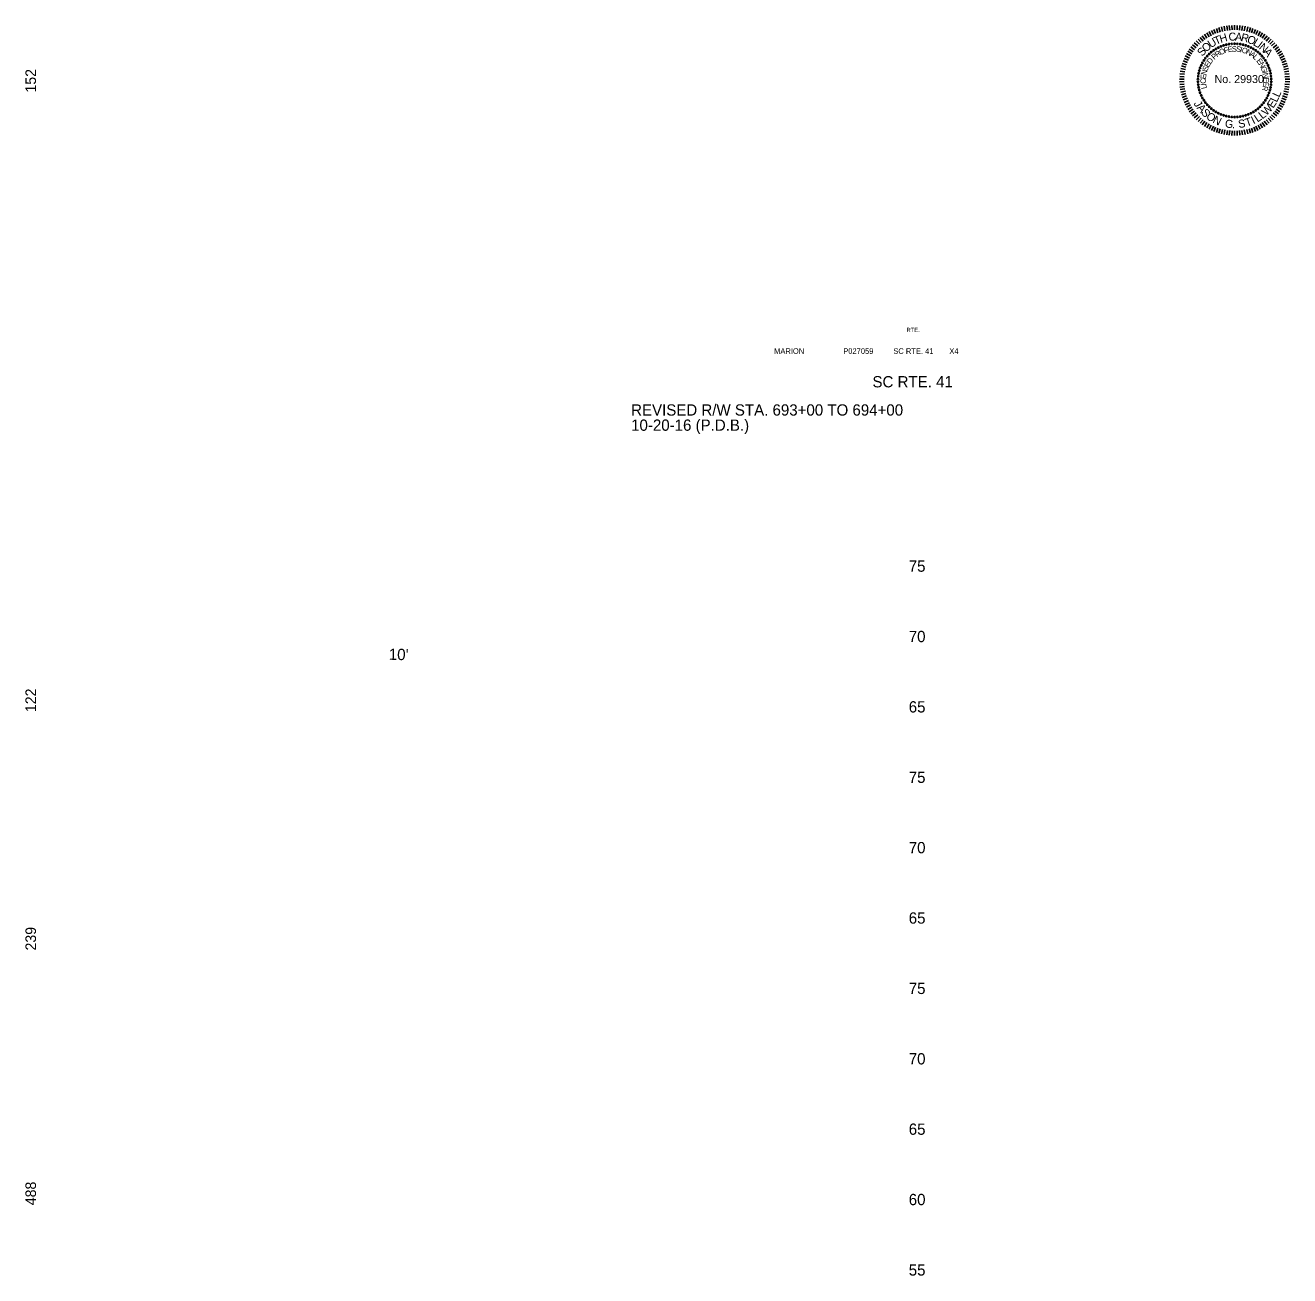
# Model space of a CAD drawing. Extents: x 952 to 1206, y 942 to 2399.
# Drawn here: x 1094.2 to 1184, y 1955 to 2043.8 of the extents above; entities that cross this region are included whole.
import ezdxf

# ---------------------------------------------------------------- set-up
doc = ezdxf.new("R2010")
doc.units = 0
for name, color, linetype in [('Default', 7, 'Continuous'), ('RD_SHT_TX', 7, 'Continuous'), ('RD_TX_PEShield', 7, 'Continuous'), ('RD_XS_TX_Elev_EX', 7, 'Continuous'), ('RD_XS_TX_Slope', 7, 'Continuous')]:
    doc.layers.add(name, color=color, linetype=linetype)

# ---------------------------------------------------------------- blocks, each defined once
blk = doc.blocks.new('STILLWELL')
at = {"layer": 'RD_TX_PEShield'}
for p, q in [((-11.93, 32.91), (-13.02, 35.99)), ((-10.28, 33.44), (-11.22, 36.57)), ((-8.61, 33.9), (-9.39, 37.07)), ((-6.92, 34.27), (-7.55, 37.48)), ((-5.21, 34.57), (-5.68, 37.8)), ((-3.49, 34.77), (-3.81, 38.03)), ((-1.76, 34.9), (-1.92, 38.16)), ((-0.03, 34.94), (-0.03, 38.21)), ((1.71, 34.9), (1.86, 38.16)), ((3.43, 34.77), (3.75, 38.03)), ((5.15, 34.57), (5.63, 37.8)), ((6.86, 34.27), (7.49, 37.48)), ((8.56, 33.9), (9.34, 37.07)), ((10.23, 33.44), (11.16, 36.57)), ((11.88, 32.91), (12.96, 35.99)), ((-25.08, 24.74), (-27.37, 27.08)), ((-23.81, 25.92), (-25.98, 28.37)), ((-22.49, 27.04), (-24.53, 29.59)), ((-21.11, 28.09), (-23.03, 30.73)), ((-19.68, 29.08), (-21.48, 31.81)), ((-18.21, 29.99), (-19.87, 32.81)), ((-16.7, 30.83), (-18.22, 33.73)), ((-15.14, 31.6), (-16.52, 34.56)), ((-13.55, 32.29), (-14.79, 35.32)), ((13.5, 32.29), (14.73, 35.32)), ((15.09, 31.6), (16.46, 34.56)), ((16.64, 30.83), (18.16, 33.73)), ((18.16, 29.99), (19.81, 32.81)), ((19.63, 29.08), (21.42, 31.81)), ((21.06, 28.09), (22.98, 30.73)), ((22.43, 27.04), (24.48, 29.59)), ((23.76, 25.92), (25.92, 28.37)), ((25.03, 24.74), (27.31, 27.08)), ((-31.38, 16.5), (-34.23, 18.09)), ((-30.5, 18), (-33.27, 19.72)), ((-29.55, 19.45), (-32.24, 21.3)), ((-28.53, 20.85), (-31.12, 22.83)), ((-27.44, 22.2), (-29.94, 24.31)), ((-26.29, 23.5), (-28.69, 25.72)), ((26.24, 23.5), (28.63, 25.72)), ((27.39, 22.2), (29.88, 24.31)), ((28.47, 20.85), (31.07, 22.83)), ((29.49, 19.45), (32.18, 21.3)), ((30.44, 18), (33.22, 19.72)), ((31.32, 16.5), (34.18, 18.09)), ((-34.64, 8.5), (-37.79, 9.35)), ((-34.14, 10.16), (-37.25, 11.17)), ((-33.57, 11.79), (-36.62, 12.95)), ((-32.91, 13.4), (-35.91, 14.7)), ((-32.18, 14.97), (-35.11, 16.42)), ((32.13, 14.97), (35.06, 16.42)), ((32.86, 13.4), (35.85, 14.7)), ((33.51, 11.79), (36.57, 12.95)), ((34.09, 10.16), (37.19, 11.17)), ((34.58, 8.5), (37.73, 9.35)), ((-35.89, -0.06), (-39.15, 0.02)), ((-35.8, 1.67), (-39.06, 1.91)), ((-35.64, 3.4), (-38.88, 3.79)), ((-35.39, 5.11), (-38.61, 5.66)), ((-35.05, 6.81), (-38.24, 7.52)), ((35, 6.81), (38.19, 7.52)), ((35.33, 5.11), (38.55, 5.66)), ((35.58, 3.4), (38.82, 3.79)), ((35.75, 1.67), (39.01, 1.91)), ((35.83, -0.06), (39.1, 0.02)), ((-35.89, -1.79), (-39.15, -1.87)), ((-35.8, -3.53), (-39.06, -3.76)), ((-35.64, -5.25), (-38.88, -5.65)), ((-35.39, -6.97), (-38.61, -7.52)), ((-35.05, -8.67), (-38.24, -9.37)), ((35, -8.67), (38.19, -9.37)), ((35.33, -6.97), (38.55, -7.52)), ((35.58, -5.25), (38.82, -5.65)), ((35.75, -3.53), (39.01, -3.76)), ((35.83, -1.79), (39.1, -1.87)), ((-34.64, -10.35), (-37.79, -11.21)), ((-34.14, -12.01), (-37.25, -13.02)), ((-33.57, -13.65), (-36.62, -14.81)), ((-32.91, -15.25), (-35.91, -16.56)), ((-32.18, -16.83), (-35.11, -18.27)), ((32.13, -16.83), (35.06, -18.27)), ((32.86, -15.25), (35.85, -16.56)), ((33.51, -13.65), (36.57, -14.81)), ((34.09, -12.01), (37.19, -13.02)), ((34.58, -10.35), (37.73, -11.21)), ((-31.38, -18.36), (-34.23, -19.95)), ((-30.5, -19.85), (-33.27, -21.58)), ((-29.55, -21.3), (-32.24, -23.16)), ((-28.53, -22.71), (-31.12, -24.69)), ((-27.44, -24.06), (-29.94, -26.16)), ((-26.29, -25.36), (-28.69, -27.58)), ((-25.08, -26.6), (-27.37, -28.93)), ((25.03, -26.6), (27.31, -28.93)), ((26.24, -25.36), (28.63, -27.58)), ((27.39, -24.06), (29.88, -26.16)), ((28.47, -22.71), (31.07, -24.69)), ((29.49, -21.3), (32.18, -23.16)), ((30.44, -19.85), (33.22, -21.58)), ((31.32, -18.36), (34.18, -19.95)), ((-23.81, -27.78), (-25.98, -30.22)), ((-22.49, -28.89), (-24.53, -31.44)), ((-21.11, -29.95), (-23.03, -32.59)), ((-19.68, -30.93), (-21.48, -33.66)), ((-18.21, -31.85), (-19.87, -34.66)), ((-16.7, -32.69), (-18.22, -35.58)), ((-15.14, -33.46), (-16.52, -36.42)), ((-13.55, -34.15), (-14.79, -37.18)), ((-11.93, -34.76), (-13.02, -37.85)), ((-10.28, -35.3), (-11.22, -38.43)), ((-8.61, -35.76), (-9.39, -38.93)), ((8.56, -35.76), (9.34, -38.93)), ((10.23, -35.3), (11.16, -38.43)), ((11.88, -34.76), (12.96, -37.85)), ((13.5, -34.15), (14.73, -37.18)), ((15.09, -33.46), (16.46, -36.42)), ((16.64, -32.69), (18.16, -35.58)), ((18.16, -31.85), (19.81, -34.66)), ((19.63, -30.93), (21.42, -33.66)), ((21.06, -29.95), (22.98, -32.59)), ((22.43, -28.89), (24.48, -31.44)), ((23.76, -27.78), (25.92, -30.22)), ((-6.92, -36.13), (-7.55, -39.34)), ((-5.21, -36.42), (-5.68, -39.65)), ((-3.49, -36.63), (-3.81, -39.88)), ((-1.76, -36.76), (-1.92, -40.02)), ((-0.03, -36.8), (-0.03, -40.06)), ((1.71, -36.76), (1.86, -40.02)), ((3.43, -36.63), (3.75, -39.88)), ((5.15, -36.42), (5.63, -39.65)), ((6.86, -36.13), (7.49, -39.34))]:
    blk.add_line(p, q, dxfattribs=at)
for centre in [(-18.09, 17.84), (-16.6, 19.17), (-15.01, 20.38), (-13.34, 21.46), (-11.59, 22.41), (-9.76, 23.23), (-7.89, 23.9), (-5.96, 24.43), (-4, 24.81), (-2.02, 25.04), (-0.03, 25.12), (1.97, 25.04), (3.95, 24.81), (5.91, 24.43), (7.83, 23.9), (9.71, 23.23), (11.53, 22.41), (13.28, 21.46), (14.96, 20.38), (16.54, 19.17), (18.03, 17.84), (-23.79, 9.73), (-22.91, 11.51), (-21.89, 13.23), (-20.74, 14.86), (-19.47, 16.4), (19.42, 16.4), (20.69, 14.86), (21.83, 13.23), (22.85, 11.51), (23.74, 9.73), (-26.05, 0.07), (-25.9, 2.06), (-25.6, 4.03), (-25.14, 5.97), (-24.54, 7.88), (24.48, 7.88), (25.09, 5.97), (25.54, 4.03), (25.85, 2.06), (26, 0.07), (-26.05, -1.93), (-25.9, -3.92), (-25.6, -5.89), (-25.14, -7.83), (25.09, -7.83), (25.54, -5.89), (25.85, -3.92), (26, -1.93), (-24.54, -9.73), (-23.79, -11.58), (-22.91, -13.37), (-21.89, -15.09), (-20.74, -16.72), (-19.47, -18.26), (19.42, -18.26), (20.69, -16.72), (21.83, -15.09), (22.85, -13.37), (23.74, -11.58), (24.48, -9.73), (-18.09, -19.69), (-16.6, -21.02), (-15.01, -22.23), (-13.34, -23.32), (-11.59, -24.27), (-9.76, -25.09), (-7.89, -25.76), (-5.96, -26.29), (-4, -26.67), (-2.02, -26.9), (-0.03, -26.97), (1.97, -26.9), (3.95, -26.67), (5.91, -26.29), (7.83, -25.76), (9.71, -25.09), (11.53, -24.27), (13.28, -23.32), (14.96, -22.23), (16.54, -21.02), (18.03, -19.69)]:
    blk.add_circle(centre, 0.49, dxfattribs=at)
for s, height, rotation, p in [('U', 5.68, 32.21524, (-16.89, 21.85)), ('T', 5.68, 23.50438, (-13.24, 24.14)), ('H', 5.68, 16.13567, (-9.92, 25.63)), ('C', 5.68, 4.07599, (-4.15, 27.11)), ('A', 5.68, 355.36513, (0.14, 27.41)), ('R', 5.68, 347.31877, (4.1, 27.11)), ('O', 5.68, 338.6079, (8.3, 26.16)), ('L', 5.68, 329.22596, (12.61, 24.44)), ('S', 5.68, 49.64355, (-22.94, 15.75)), ('O', 5.68, 41.59718, (-20.38, 18.79)), ('P', 3.92, 41.0022, (-14.52, 13.51)), ('R', 3.92, 33.30566, (-12.46, 15.32)), ('O', 3.92, 24.97351, (-9.98, 16.95)), ('F', 3.92, 15.99945, (-7.07, 18.28)), ('E', 3.92, 8.95111, (-4.65, 19)), ('S', 3.92, 1.25456, (-1.94, 19.44)), ('S', 3.92, 353.55802, (0.8, 19.51)), ('I', 3.92, 345.86148, (3.53, 19.22)), ('O', 3.92, 342.65826, (4.65, 18.99)), ('N', 3.92, 333.6842, (7.7, 18.01)), ('A', 3.92, 325.35205, (10.36, 16.69)), ('I', 5.68, 322.52176, (15.48, 22.79)), ('N', 5.68, 319.17294, (16.84, 21.84)), ('A', 5.68, 310.46208, (20.09, 19.02)), ('S', 3.92, 67.93066, (-19.49, 5.38)), ('E', 3.92, 60.23412, (-18.47, 7.93)), ('D', 3.92, 52.53758, (-17.12, 10.32)), ('L', 3.92, 317.65551, (12.63, 15.14)), ('E', 3.92, 308.03955, (15.14, 12.8)), ('N', 3.92, 300.34301, (16.84, 10.65)), ('C', 3.92, 92.29151, (-20.36, -3.21)), ('E', 3.92, 83.95936, (-20.47, -0.24)), ('N', 3.92, 76.26281, (-20.2, 2.49)), ('G', 3.92, 292.01086, (18.34, 8.08)), ('I', 3.92, 283.0368, (19.52, 5.11)), ('N', 3.92, 279.83358, (19.83, 4.01)), ('E', 3.92, 271.50143, (20.33, 1.08)), ('I', 3.92, 95.49473, (-20.2, -4.35)), ('L', 3.92, 101.90747, (-19.69, -6.58)), ('R', 3.92, 256.10834, (20.13, -4.4)), ('E', 3.92, 263.80489, (20.42, -1.67)), ('J', 5.68, 299.03302, (-29.35, -17.26)), ('W', 5.68, 47.05177, (22.62, -26.41)), ('E', 5.68, 56.4327, (27.3, -21.12)), ('L', 5.68, 65.09801, (29.98, -16.89)), ('L', 5.68, 65.09801, (31.58, -13.34)), ('A', 5.68, 310.58873, (-27.19, -20.61)), ('S', 5.68, 310.58873, (-24.3, -23.99)), ('O', 5.68, 321.00719, (-20.82, -27.39)), ('N', 5.68, 333.43256, (-16.05, -30.75)), ('I', 5.68, 25.39911, (13.3, -32.17)), ('L', 5.68, 34.06442, (16.21, -30.92)), ('L', 5.68, 37.67084, (19.57, -28.72)), ('G', 5.68, 352.2045, (-7.22, -34.2)), ('.', 5.68, 0.86982, (-1.8, -34.9)), ('S', 5.68, 8.08265, (2.93, -34.79)), ('T', 5.68, 18.90189, (8.5, -33.88))]:
    blk.add_text(s, height=height, rotation=rotation, dxfattribs=at).set_placement(p)
blk.add_text('No. 29930', height=5.685, dxfattribs=at).set_placement((-14.3, -2.84))

msp = doc.modelspace()

# ---------------------------------------------------------------- block references
at = {"layer": 'Default', "xscale": 0.1, "yscale": 0.10000000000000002}
msp.add_blockref('STILLWELL', (1180.075, 2040), dxfattribs=at)

# ---------------------------------------------------------------- texts
at = {"layer": 'Default'}
for s, p in [('152', (1094.913, 2039.042)), ('122', (1094.913, 1995.029)), ('239', (1094.913, 1978.091)), ('488', (1094.913, 1959.996))]:
    msp.add_text(s, height=0.75, rotation=90, dxfattribs=at).set_placement(p)
at = {"layer": 'RD_SHT_TX'}
for s, height, p in [('RTE.', 0.3, (1156.759, 2022.03)), ('MARION', 0.4, (1147.353, 2020.476)), ('P027059', 0.4, (1152.265, 2020.476)), ('SC RTE. 41', 0.4, (1155.822, 2020.476)), ('X4', 0.4, (1159.803, 2020.476)), ('SC RTE. 41', 0.8, (1154.342, 2018.098)), ('REVISED R/W STA. 693+00 TO 694+00', 0.8, (1137.195, 2016.093)), ('10-20-16 (P.D.B.)', 0.8, (1137.195, 2015.015))]:
    msp.add_text(s, height=height, dxfattribs=at).set_placement(p)
at = {"layer": 'RD_XS_TX_Elev_EX'}
for s, p in [('75', (1156.919, 2005)), ('70', (1156.919, 2000)), ('65', (1156.919, 1995)), ('75', (1156.919, 1990)), ('70', (1156.919, 1985)), ('65', (1156.919, 1980)), ('75', (1156.919, 1975)), ('70', (1156.919, 1970)), ('65', (1156.919, 1965)), ('60', (1156.919, 1960)), ('55', (1156.919, 1955))]:
    msp.add_text(s, height=0.8, dxfattribs=at).set_placement(p)
at = {"layer": 'RD_XS_TX_Slope'}
msp.add_text("10'", height=0.8, rotation=358.34568, dxfattribs=at).set_placement((1119.969, 1998.749))

doc.saveas('drawing.dxf')
